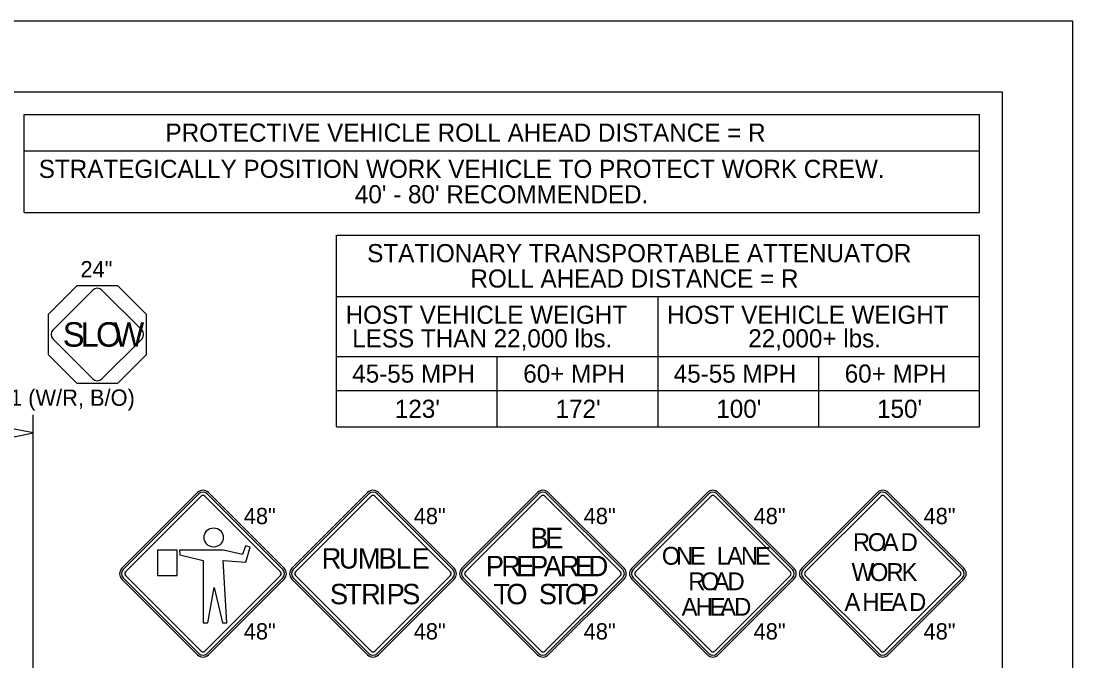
# Model space of a CAD drawing. Extents: x 99999.1 to 100095.7, y 99995 to 100010.7.
# Drawn here: x 100011.42 to 100016.062, y 100007.863 to 100010.687 of the extents above; entities that cross this region are included whole.
import ezdxf

# ---------------------------------------------------------------- set-up
doc = ezdxf.new("R2010")
doc.units = 0
for name, color, linetype in [('Default', 7, 'Continuous'), ('SH_GI_PlotLimits', 7, 'Continuous'), ('SH_GI_SheetBorder', 7, 'Continuous'), ('SH_TI_Tables', 7, 'Continuous'), ('TR_SN_ConstructionSigns', 7, 'Continuous'), ('TR_WZ_WorkZoneDetails', 7, 'Continuous')]:
    doc.layers.add(name, color=color, linetype=linetype)

msp = doc.modelspace()

# ---------------------------------------------------------------- linework, layer by layer
at = {"layer": 'Default'}
for p, q in [((100012.9495, 100008.6062), (100012.6154, 100008.2721)), ((100013.3313, 100008.2721), (100012.9972, 100008.6062)), ((100012.6154, 100008.2243), (100012.9495, 100007.8902)), ((100012.9972, 100007.8902), (100013.3313, 100008.2243))]:
    msp.add_line(p, q, dxfattribs=at)
for centre, start, end in [((100012.9733, 100008.5823), 45, 135), ((100012.6392, 100008.2482), 135, 225), ((100013.3075, 100008.2482), 315, 45), ((100012.9733, 100007.9141), 225, 315)]:
    msp.add_arc(centre, 0.0338, start, end, dxfattribs=at)
at = {"layer": 'SH_GI_PlotLimits'}
msp.add_lwpolyline([(99999.0625, 99999.6875), (100016.0625, 99999.6875), (100016.0625, 100010.6875), (99999.0625, 100010.6875)], close=True, dxfattribs=at)
at = {"layer": 'SH_GI_SheetBorder'}
for p, q in [((100000, 100010.375), (100015.75, 100010.375)), ((100015.75, 100010.375), (100015.75, 100000))]:
    msp.add_line(p, q, dxfattribs=at)
at = {"layer": 'SH_TI_Tables'}
for p, q in [((100011.4347, 100009.843), (100011.4347, 100010.275)), ((100011.4347, 100010.275), (100015.65, 100010.275)), ((100015.65, 100009.843), (100015.65, 100010.275)), ((100011.4347, 100010.115), (100015.65, 100010.115)), ((100011.4347, 100009.843), (100015.65, 100009.843)), ((100012.8126, 100008.896), (100012.8126, 100009.743)), ((100012.8156, 100009.743), (100015.65, 100009.743)), ((100015.65, 100008.896), (100015.65, 100009.743)), ((100012.8126, 100009.471), (100015.65, 100009.471)), ((100014.2313, 100008.896), (100014.2313, 100009.471)), ((100012.8126, 100009.2069), (100014.2313, 100009.2069)), ((100013.5219, 100008.896), (100013.5219, 100009.2069)), ((100014.2313, 100009.2069), (100015.65, 100009.2069)), ((100014.9406, 100008.896), (100014.9406, 100009.2069)), ((100012.8126, 100009.056), (100014.2313, 100009.056)), ((100014.2313, 100009.056), (100015.65, 100009.056)), ((100012.8126, 100008.896), (100015.65, 100008.896))]:
    msp.add_line(p, q, dxfattribs=at)
at = {"layer": 'TR_SN_ConstructionSigns'}
for p, q in [((100011.7367, 100009.4997), (100011.5615, 100009.3245)), ((100011.9527, 100009.3245), (100011.7775, 100009.4997)), ((100011.5615, 100009.2837), (100011.7367, 100009.1085)), ((100011.7775, 100009.1085), (100011.9527, 100009.2837)), ((100012.1995, 100008.6062), (100011.8654, 100008.2721)), ((100012.2055, 100008.6002), (100011.8713, 100008.2661)), ((100011.8813, 100008.2561), (100012.2154, 100008.5903)), ((100012.2313, 100008.5903), (100012.5654, 100008.2561)), ((100012.5754, 100008.2661), (100012.2412, 100008.6002)), ((100012.5813, 100008.2721), (100012.2472, 100008.6062)), ((100012.6154, 100008.2721), (100012.9495, 100008.6062)), ((100012.9555, 100008.6002), (100012.6213, 100008.2661)), ((100012.6313, 100008.2561), (100012.9654, 100008.5903)), ((100012.9813, 100008.5903), (100013.3154, 100008.2561)), ((100013.3254, 100008.2661), (100012.9912, 100008.6002)), ((100012.9972, 100008.6062), (100013.3313, 100008.2721)), ((100013.6995, 100008.6062), (100013.3654, 100008.2721)), ((100013.7055, 100008.6002), (100013.3713, 100008.2661)), ((100013.3813, 100008.2561), (100013.7154, 100008.5903)), ((100013.7313, 100008.5903), (100014.0654, 100008.2561)), ((100014.0754, 100008.2661), (100013.7412, 100008.6002)), ((100014.0813, 100008.2721), (100013.7472, 100008.6062)), ((100014.4495, 100008.6062), (100014.1154, 100008.2721)), ((100014.4555, 100008.6002), (100014.1213, 100008.2661)), ((100014.1313, 100008.2561), (100014.4654, 100008.5903)), ((100014.4813, 100008.5903), (100014.8154, 100008.2561)), ((100014.8254, 100008.2661), (100014.4912, 100008.6002)), ((100014.8313, 100008.2721), (100014.4972, 100008.6062)), ((100015.1995, 100008.6062), (100014.8654, 100008.2721)), ((100015.2055, 100008.6002), (100014.8713, 100008.2661)), ((100014.8813, 100008.2561), (100015.2154, 100008.5903)), ((100015.2313, 100008.5903), (100015.5654, 100008.2561)), ((100015.5754, 100008.2661), (100015.2412, 100008.6002)), ((100015.5813, 100008.2721), (100015.2472, 100008.6062)), ((100011.8654, 100008.2243), (100012.1995, 100007.8902)), ((100011.8713, 100008.2303), (100012.2055, 100007.8962)), ((100012.2154, 100007.9061), (100011.8813, 100008.2402)), ((100012.5654, 100008.2402), (100012.2313, 100007.9061)), ((100012.2412, 100007.8962), (100012.5754, 100008.2303)), ((100012.2472, 100007.8902), (100012.5813, 100008.2243)), ((100012.9495, 100007.8902), (100012.6154, 100008.2243)), ((100012.6213, 100008.2303), (100012.9555, 100007.8962)), ((100012.9654, 100007.9061), (100012.6313, 100008.2402)), ((100013.3154, 100008.2402), (100012.9813, 100007.9061)), ((100012.9912, 100007.8962), (100013.3254, 100008.2303)), ((100013.3313, 100008.2243), (100012.9972, 100007.8902)), ((100013.3654, 100008.2243), (100013.6995, 100007.8902)), ((100013.3713, 100008.2303), (100013.7055, 100007.8962)), ((100013.7154, 100007.9061), (100013.3813, 100008.2402)), ((100014.0654, 100008.2402), (100013.7313, 100007.9061)), ((100013.7412, 100007.8962), (100014.0754, 100008.2303)), ((100013.7472, 100007.8902), (100014.0813, 100008.2243)), ((100014.1154, 100008.2243), (100014.4495, 100007.8902)), ((100014.1213, 100008.2303), (100014.4555, 100007.8962)), ((100014.4654, 100007.9061), (100014.1313, 100008.2402)), ((100014.8154, 100008.2402), (100014.4813, 100007.9061)), ((100014.4912, 100007.8962), (100014.8254, 100008.2303)), ((100014.4972, 100007.8902), (100014.8313, 100008.2243)), ((100014.8654, 100008.2243), (100015.1995, 100007.8902)), ((100014.8713, 100008.2303), (100015.2055, 100007.8962)), ((100015.2154, 100007.9061), (100014.8813, 100008.2402)), ((100015.5654, 100008.2402), (100015.2313, 100007.9061)), ((100015.2412, 100007.8962), (100015.5754, 100008.2303)), ((100015.2472, 100007.8902), (100015.5813, 100008.2243))]:
    msp.add_line(p, q, dxfattribs=at)
for points in [[(100011.9731, 100009.3936), (100011.9731, 100009.2146), (100011.8466, 100009.0881), (100011.6676, 100009.0881), (100011.5411, 100009.2146), (100011.5411, 100009.3936), (100011.6676, 100009.5201), (100011.8466, 100009.5201)], [(100012.0221, 100008.3523), (100012.0221, 100008.2401), (100012.1097, 100008.2401), (100012.1097, 100008.3523)], [(100012.12, 100008.3526), (100012.1213, 100008.3309), (100012.2239, 100008.307), (100012.2239, 100008.0307), (100012.2439, 100008.0307), (100012.272, 100008.1877), (100012.3095, 100008.0307), (100012.3285, 100008.0307), (100012.3119, 100008.3069), (100012.4122, 100008.2988), (100012.4311, 100008.3658), (100012.4104, 100008.3717), (100012.3972, 100008.3334), (100012.3143, 100008.3526)]]:
    msp.add_lwpolyline(points, close=True, dxfattribs=at)
msp.add_circle((100012.2703, 100008.4081), 0.0424, dxfattribs=at)
for centre, radius, start, end in [((100011.7571, 100009.4794), 0.0288, 45, 135), ((100011.5818, 100009.3041), 0.0288, 135, 225), ((100011.9324, 100009.3041), 0.0288, 315, 45), ((100011.7571, 100009.1288), 0.0288, 225, 315), ((100012.2233, 100008.5823), 0.0338, 45, 135), ((100012.2233, 100008.5823), 0.0253, 45, 135), ((100012.2233, 100008.5823), 0.0113, 45, 135), ((100012.9733, 100008.5823), 0.0338, 45, 135), ((100012.9733, 100008.5823), 0.0253, 45, 135), ((100012.9733, 100008.5823), 0.0113, 45, 135), ((100013.7233, 100008.5823), 0.0338, 45, 135), ((100013.7233, 100008.5823), 0.0253, 45, 135), ((100013.7233, 100008.5823), 0.0113, 45, 135), ((100014.4733, 100008.5823), 0.0338, 45, 135), ((100014.4733, 100008.5823), 0.0253, 45, 135), ((100014.4733, 100008.5823), 0.0113, 45, 135), ((100015.2233, 100008.5823), 0.0338, 45, 135), ((100015.2233, 100008.5823), 0.0253, 45, 135), ((100015.2233, 100008.5823), 0.0113, 45, 135), ((100011.8892, 100008.2482), 0.0338, 135, 225), ((100011.8892, 100008.2482), 0.0253, 135, 225), ((100011.8892, 100008.2482), 0.0113, 135, 225), ((100012.5575, 100008.2482), 0.0113, 315, 45), ((100012.5575, 100008.2482), 0.0253, 315, 45), ((100012.5575, 100008.2482), 0.0338, 315, 45), ((100012.6392, 100008.2482), 0.0338, 135, 225), ((100012.6392, 100008.2482), 0.0253, 135, 225), ((100012.6392, 100008.2482), 0.0113, 135, 225), ((100013.3075, 100008.2482), 0.0113, 315, 45), ((100013.3075, 100008.2482), 0.0253, 315, 45), ((100013.3075, 100008.2482), 0.0338, 315, 45), ((100013.3892, 100008.2482), 0.0338, 135, 225), ((100013.3892, 100008.2482), 0.0253, 135, 225), ((100013.3892, 100008.2482), 0.0113, 135, 225), ((100014.0575, 100008.2482), 0.0113, 315, 45), ((100014.0575, 100008.2482), 0.0253, 315, 45), ((100014.0575, 100008.2482), 0.0338, 315, 45), ((100014.1392, 100008.2482), 0.0338, 135, 225), ((100014.1392, 100008.2482), 0.0253, 135, 225), ((100014.1392, 100008.2482), 0.0113, 135, 225), ((100014.8075, 100008.2482), 0.0113, 315, 45), ((100014.8075, 100008.2482), 0.0253, 315, 45), ((100014.8075, 100008.2482), 0.0338, 315, 45), ((100014.8892, 100008.2482), 0.0338, 135, 225), ((100014.8892, 100008.2482), 0.0253, 135, 225), ((100014.8892, 100008.2482), 0.0113, 135, 225), ((100015.5575, 100008.2482), 0.0113, 315, 45), ((100015.5575, 100008.2482), 0.0253, 315, 45), ((100015.5575, 100008.2482), 0.0338, 315, 45), ((100012.2233, 100007.9141), 0.0338, 225, 315), ((100012.2233, 100007.9141), 0.0253, 225, 315), ((100012.2233, 100007.9141), 0.0113, 225, 315), ((100012.9733, 100007.9141), 0.0338, 225, 315), ((100012.9733, 100007.9141), 0.0253, 225, 315), ((100012.9733, 100007.9141), 0.0113, 225, 315), ((100013.7233, 100007.9141), 0.0338, 225, 315), ((100013.7233, 100007.9141), 0.0253, 225, 315), ((100013.7233, 100007.9141), 0.0113, 225, 315), ((100014.4733, 100007.9141), 0.0338, 225, 315), ((100014.4733, 100007.9141), 0.0253, 225, 315), ((100014.4733, 100007.9141), 0.0113, 225, 315), ((100015.2233, 100007.9141), 0.0338, 225, 315), ((100015.2233, 100007.9141), 0.0253, 225, 315), ((100015.2233, 100007.9141), 0.0113, 225, 315)]:
    msp.add_arc(centre, radius, start, end, dxfattribs=at)
at = {"layer": 'TR_WZ_WorkZoneDetails'}
msp.add_line((100011.4733, 100007.0923), (100011.4733, 100008.9491), dxfattribs=at)
msp.add_lwpolyline([(100011.4733, 100008.8691), (100011.3751, 100008.8884), (100011.3796, 100008.8691), (100011.3751, 100008.8498)], close=True, dxfattribs=at)

# ---------------------------------------------------------------- texts
at = {"layer": 'Default'}
for s, p in [('R', (100012.747, 100008.2707)), ('U', (100012.8235, 100008.2707)), ('M', (100012.9063, 100008.2707)), ('B', (100012.9981, 100008.2707)), ('L', (100013.0746, 100008.2707)), ('E', (100013.1439, 100008.2707)), ('S', (100012.7834, 100008.1132)), ('S', (100013.102, 100008.1132)), ('T', (100012.8518, 100008.1132)), ('R', (100012.9211, 100008.1132)), ('I', (100012.9976, 100008.1132)), ('P', (100013.0336, 100008.1132))]:
    msp.add_text(s, height=0.09, dxfattribs=at).set_placement(p)
at = {"layer": 'SH_TI_Tables'}
for s, p in [('PROTECTIVE VEHICLE ROLL AHEAD DISTANCE = R', (100012.0577, 100010.155)), ('STRATEGICALLY POSITION WORK VEHICLE TO PROTECT WORK CREW.', (100011.4984, 100009.995)), ("40' - 80'", (100012.8935, 100009.883)), ('RECOMMENDED.', (100013.297, 100009.883)), ('STATIONARY TRANSPORTABLE ATTENUATOR', (100012.9479, 100009.623)), ('ROLL AHEAD DISTANCE = R', (100013.4035, 100009.511)), ('HOST VEHICLE WEIGHT', (100012.8526, 100009.351)), ('HOST VEHICLE WEIGHT', (100014.2713, 100009.351)), ('LESS THAN 22,000 lbs.', (100012.8817, 100009.2469)), ('22,000+ lbs.', (100014.6295, 100009.2469)), ('45-55 MPH', (100012.8818, 100009.0914)), ('60+ MPH', (100013.6365, 100009.0914)), ('45-55 MPH', (100014.3006, 100009.0914)), ('60+ MPH', (100015.0552, 100009.0914)), ("123'", (100013.0698, 100008.936)), ("172'", (100013.7792, 100008.936)), ("100'", (100014.4885, 100008.936)), ("150'", (100015.1979, 100008.936))]:
    msp.add_text(s, height=0.08, dxfattribs=at).set_placement(p)
at = {"layer": 'TR_SN_ConstructionSigns'}
for s, height, p in [('24"', 0.072, (100011.6824, 100009.5561)), ('S', 0.108, (100011.6043, 100009.2501)), ('L', 0.108, (100011.6831, 100009.2501)), ('O', 0.108, (100011.7512, 100009.2501)), ('W', 0.108, (100011.8279, 100009.2501)), ('B', 0.09, (100013.6675, 100008.3607)), ('E', 0.09, (100013.7332, 100008.3607)), ('R', 0.0788, (100015.0914, 100008.348)), ('O', 0.0788, (100015.1568, 100008.348)), ('A', 0.0788, (100015.223, 100008.348)), ('D', 0.0788, (100015.3017, 100008.348)), ('O', 0.0787, (100014.2481, 100008.2876)), ('N', 0.0787, (100014.3103, 100008.2876)), ('E', 0.0787, (100014.3718, 100008.2876)), ('L', 0.0787, (100014.4907, 100008.2876)), ('A', 0.0787, (100014.5356, 100008.2876)), ('N', 0.0787, (100014.597, 100008.2876)), ('E', 0.0787, (100014.6584, 100008.2876)), ('P', 0.09, (100013.4713, 100008.2369)), ('R', 0.09, (100013.5397, 100008.2369)), ('E', 0.09, (100013.6054, 100008.2369)), ('P', 0.09, (100013.6666, 100008.2369)), ('A', 0.09, (100013.7278, 100008.2369)), ('R', 0.09, (100013.798, 100008.2369)), ('E', 0.09, (100013.8637, 100008.2369)), ('D', 0.09, (100013.9249, 100008.2369)), ('R', 0.0787, (100014.3647, 100008.1751)), ('O', 0.0787, (100014.4206, 100008.1751)), ('A', 0.0787, (100014.4765, 100008.1751)), ('D', 0.0787, (100014.5379, 100008.1751)), ('W', 0.0788, (100015.0855, 100008.2158)), ('O', 0.0788, (100015.1659, 100008.2158)), ('R', 0.0788, (100015.2391, 100008.2158)), ('K', 0.0788, (100015.306, 100008.2158)), ('O', 0.09, (100013.5618, 100008.1132)), ('S', 0.09, (100013.7049, 100008.1132)), ('O', 0.09, (100013.8201, 100008.1132)), ('T', 0.09, (100013.5051, 100008.1132)), ('T', 0.09, (100013.7634, 100008.1132)), ('P', 0.09, (100013.8912, 100008.1132)), ('A', 0.0788, (100015.054, 100008.0837)), ('H', 0.0788, (100015.1328, 100008.0837)), ('E', 0.0788, (100015.2052, 100008.0837)), ('A', 0.0788, (100015.2604, 100008.0837)), ('D', 0.0788, (100015.3391, 100008.0837)), ('A', 0.0787, (100014.3355, 100008.0626)), ('H', 0.0787, (100014.397, 100008.0626)), ('E', 0.0787, (100014.4584, 100008.0626)), ('A', 0.0787, (100014.5056, 100008.0626)), ('D', 0.0787, (100014.5671, 100008.0626))]:
    msp.add_text(s, height=height, dxfattribs=at).set_placement(p)
for s, p in [('W21-1201 (W/R, B/O)', (100010.9809, 100008.9891)), ('48"', (100012.4031, 100008.4667)), ('48"', (100013.1531, 100008.4667)), ('48"', (100013.9031, 100008.4667)), ('48"', (100014.6531, 100008.4667)), ('48"', (100015.4031, 100008.4667)), ('48"', (100012.4031, 100007.9576)), ('48"', (100013.1531, 100007.9576)), ('48"', (100013.9031, 100007.9576)), ('48"', (100014.6531, 100007.9576)), ('48"', (100015.4031, 100007.9576))]:
    msp.add_text(s, height=0.072, rotation=360, dxfattribs=at).set_placement(p)

doc.saveas('drawing.dxf')
